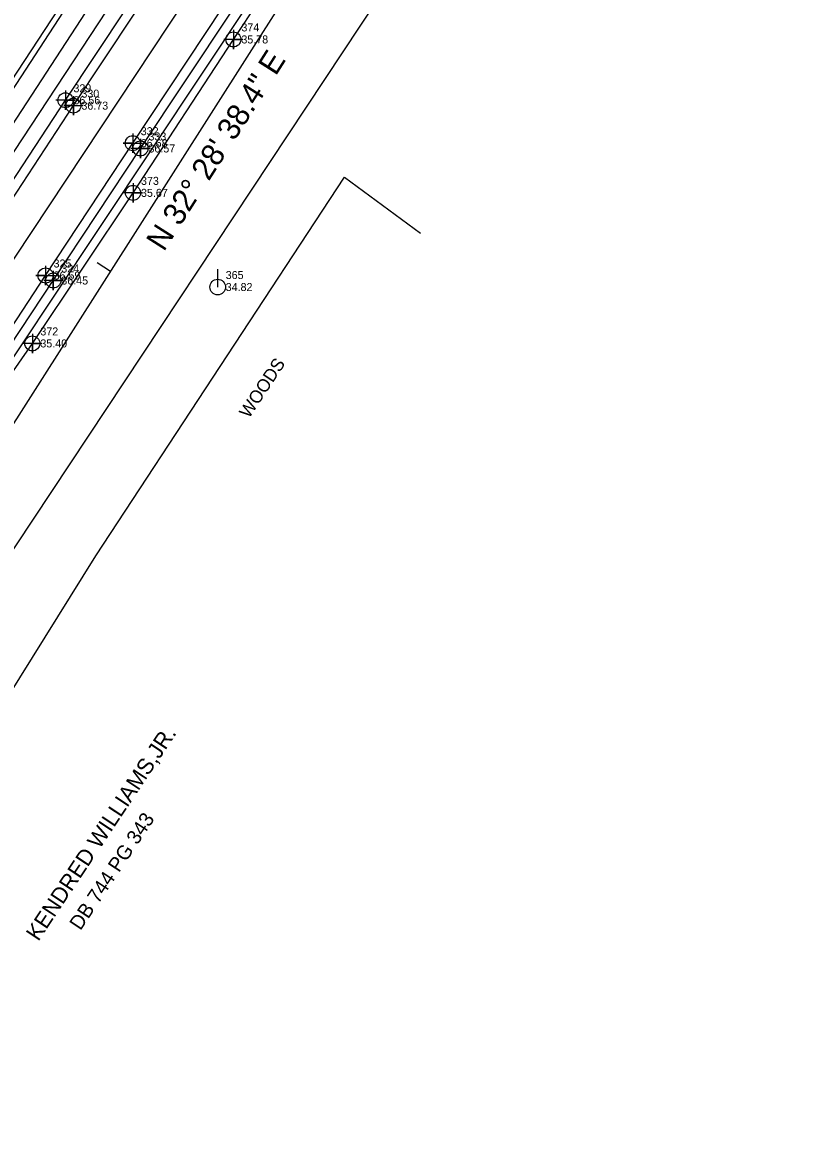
# Model space of a CAD drawing. Extents: x 2603627 to 2605187, y 896619 to 899063.
# Drawn here: x 2604841.7 to 2605082.8, y 898327.7 to 898680.4 of the extents above; entities that cross this region are included whole.
import ezdxf

# ---------------------------------------------------------------- set-up
doc = ezdxf.new("R2010")
doc.units = 0
for name, color, linetype in [('Exist Horizontal Alignment', 7, 'Continuous'), ('Exist Horizontal Baseline Alignment', 7, 'Continuous'), ('Exist Horizontal Baseline Alignment Direction Label', 7, 'Continuous'), ('Exist Horizontal Baseline Alignment Tick small', 7, 'Continuous'), ('Exist Property Deed Book Text', 7, 'Continuous'), ('Exist Property Owner Text', 7, 'Continuous'), ('Exist Right of Way Line', 7, 'Continuous'), ('Exist Roads EOP', 7, 'Continuous'), ('Exist Roads EOP Cogo Elevation', 7, 'Continuous'), ('Exist Roads EOP Cogo Number', 7, 'Continuous'), ('Exist Roads EOP Cogo Point CELL', 7, 'Continuous'), ('Exist Roads EOT', 7, 'Continuous'), ('Exist Roads EOT Cogo Elevation', 7, 'Continuous'), ('Exist Roads EOT Cogo Number', 7, 'Continuous'), ('Exist Roads EOT Cogo Point CELL', 7, 'Continuous'), ('Exist Utilities Power Pole CELL', 7, 'Continuous'), ('Exist Utilities Power Pole Cogo Elevation', 7, 'Continuous'), ('Exist Utilities Power Pole Cogo Number', 7, 'Continuous'), ('Exist Utilities Telephone UG Cable SUE LOS C', 7, 'Continuous'), ('Exist Utilities Telephone UG FO SUE LOS C', 7, 'Continuous'), ('Exist Utilities Water UG Line SUE LOS B', 7, 'Continuous'), ('Exist Utilities Water UG Line SUE LOS B Cogo Elevation', 7, 'Continuous'), ('Exist Utilities Water UG Line SUE LOS B Cogo Number', 7, 'Continuous'), ('Exist Utilities Water UG Line SUE LOS B Cogo Point CELL', 7, 'Continuous'), ('Exist Vegetation Woods Line', 7, 'Continuous'), ('Exist Vegetation Woods Line Text', 7, 'Continuous')]:
    doc.layers.add(name, color=color, linetype=linetype)

# ---------------------------------------------------------------- blocks, each defined once
blk = doc.blocks.new('EXIST ROADS EOP COGO POINT')
at = {"layer": 'Exist Roads EOP Cogo Point CELL'}
blk.add_lwpolyline([(0, 0.06), (0, -0.06), (0, 0), (0.06, 0), (-0.06, 0)], dxfattribs=at)
blk.add_circle((0, 0), 0.0469, dxfattribs=at)
blk = doc.blocks.new('EXIST ROADS EOT COGO POINT')
at = {"layer": 'Exist Roads EOT Cogo Point CELL'}
blk.add_lwpolyline([(0, 0.06), (0, -0.06), (0, 0), (-0.06, 0), (0.06, 0)], dxfattribs=at)
blk.add_circle((0, 0), 0.0469, dxfattribs=at)
blk = doc.blocks.new('EXIST UTILITIES WATER UG LINE SUE LOS B COGO POINT')
at = {"layer": 'Exist Utilities Water UG Line SUE LOS B Cogo Point CELL'}
blk.add_lwpolyline([(0, 0.06), (0, -0.06), (0, 0), (0.06, 0), (-0.06, 0)], dxfattribs=at)
blk.add_circle((0, 0), 0.0469, dxfattribs=at)

msp = doc.modelspace()

# ---------------------------------------------------------------- linework, layer by layer
at = {"layer": 'Exist Horizontal Alignment'}
msp.add_line((2604681.44, 898368.79), (2605041.11, 898911.74), dxfattribs=at)
at = {"layer": 'Exist Horizontal Baseline Alignment'}
msp.add_line((2604793.6, 898483.9), (2605028.26, 898852.56), dxfattribs=at)
at = {"layer": 'Exist Horizontal Baseline Alignment Tick small'}
msp.add_line((2604869.2, 898602.67), (2604864.98, 898605.35), dxfattribs=at)
at = {"layer": 'Exist Right of Way Line'}
msp.add_line((2604723.13, 898341.18), (2605082.79, 898884.13), dxfattribs=at)
at = {"layer": 'Exist Roads EOP'}
for points in [[(2604577.96, 898237.27), (2604606.45, 898281.24), (2604633.89, 898322.5), (2604662.45, 898365.47), (2604690.62, 898408.06), (2604717.29, 898448.09), (2604745.46, 898490.11), (2604773.6, 898532.6), (2604800.88, 898573.95), (2604828.34, 898615.46), (2604855.1, 898656.15), (2604883.53, 898699.09), (2604911.29, 898740.95), (2604939.38, 898783.41), (2604966.33, 898824.04), (2604993.38, 898865.27), (2605022.2, 898908.38), (2605029.46, 898919.46)], [(2604713.86, 898392.44), (2604740.28, 898432.25), (2604768.45, 898474.26), (2604797.27, 898517.92), (2604823.93, 898558.47), (2604851.31, 898599.84), (2604878.52, 898641.09), (2604906.84, 898683.65), (2604934.68, 898725.71), (2604962.63, 898767.92), (2604989.32, 898808.49), (2605016.42, 898849.59), (2605045.34, 898893.33), (2605052.55, 898904.16)]]:
    msp.add_lwpolyline(points, dxfattribs=at)
at = {"layer": 'Exist Roads EOT'}
for points in [[(2604580.65, 898235.67), (2604609.23, 898279.3), (2604636.66, 898320.72), (2604665.18, 898363.91), (2604693.37, 898406.36), (2604719.95, 898446.05), (2604748, 898488.34), (2604776.15, 898530.84), (2604803.5, 898572.3), (2604830.95, 898613.91), (2604857.58, 898654.47), (2604886.02, 898697.38), (2604913.86, 898739.33), (2604942.03, 898781.72), (2604969.06, 898822.38), (2604996.07, 898863.44), (2605024.73, 898906.73), (2605032, 898917.78)], [(2604598.04, 898223.4), (2604627.23, 898267.23), (2604654.64, 898308.57), (2604683.28, 898352.01), (2604711.27, 898394.14), (2604737.98, 898434.05), (2604766.04, 898475.94), (2604794.96, 898519.26), (2604821.61, 898559.82), (2604848.89, 898601.4), (2604876.12, 898642.73), (2604904.4, 898685.35), (2604932.33, 898727.23), (2604960.29, 898769.49), (2604987.32, 898810.19), (2605014.12, 898850.95), (2605043.08, 898894.89), (2605050.2, 898905.72)]]:
    msp.add_lwpolyline(points, dxfattribs=at)
at = {"layer": 'Exist Utilities Power Pole CELL'}
for q in [(2604902.65, 898603.41), (2604902.65, 898597.79)]:
    msp.add_line((2604902.65, 898597.79), q, dxfattribs=at)
msp.add_circle((2604902.65, 898597.79), 2.45, dxfattribs=at)
at = {"layer": 'Exist Utilities Telephone UG Cable SUE LOS C'}
for p, q in [((2604797.03, 898576.37), (2605024.91, 898922.48)), ((2604850.74, 898593.69), (2605031.63, 898865.69)), ((2604658.71, 898389.49), (2604852.96, 898684.66)), ((2604753.32, 898447.21), (2604850.74, 898593.69))]:
    msp.add_line(p, q, dxfattribs=at)
at = {"layer": 'Exist Utilities Telephone UG FO SUE LOS C'}
for p, q in [((2604671.2, 898402.26), (2605014.35, 898929.48)), ((2604676.14, 898398.98), (2605019.3, 898926.2))]:
    msp.add_line(p, q, dxfattribs=at)
at = {"layer": 'Exist Utilities Water UG Line SUE LOS B'}
msp.add_lwpolyline([(2604590.41, 898183.07), (2604608.13, 898210.78), (2604631.33, 898247.72), (2604631.98, 898248.77), (2604637.93, 898260.9), (2604650.01, 898281.75), (2604670.13, 898312.66), (2604706.14, 898370.49), (2604744.2, 898428.79), (2604775.85, 898478.14), (2604817.62, 898541.22), (2604844.76, 898580.18), (2604876.2, 898627.22), (2604907.55, 898675.15), (2604931.69, 898711.47), (2604963.51, 898758.63), (2604991.08, 898800.9), (2605022.23, 898847.26), (2605044.13, 898880.13), (2605057.71, 898900.74)], dxfattribs=at)
at = {"layer": 'Exist Vegetation Woods Line'}
for points in [[(2604864.62, 898513.8), (2604942.25, 898632.13), (2604965.96, 898614.62)], [(2604653.24, 898142.95), (2604632.09, 898155.82), (2604674.87, 898231.68), (2604758.69, 898344.01), (2604864.62, 898513.8)]]:
    msp.add_lwpolyline(points, dxfattribs=at)

# ---------------------------------------------------------------- block references
at = {"layer": 'Exist Roads EOP Cogo Point CELL', "xscale": 50, "yscale": 50}
for p in [(2604855.1, 898656.15), (2604878.52, 898641.09), (2604851.31, 898599.84)]:
    msp.add_blockref('EXIST ROADS EOP COGO POINT', p, dxfattribs=at)
at = {"layer": 'Exist Roads EOT Cogo Point CELL', "xscale": 50, "yscale": 50}
for p in [(2604857.58, 898654.47), (2604876.12, 898642.73), (2604848.89, 898601.4)]:
    msp.add_blockref('EXIST ROADS EOT COGO POINT', p, dxfattribs=at)
at = {"layer": 'Exist Utilities Water UG Line SUE LOS B Cogo Point CELL', "xscale": 50, "yscale": 50}
for p in [(2604907.55, 898675.15), (2604876.2, 898627.22), (2604844.76, 898580.18)]:
    msp.add_blockref('EXIST UTILITIES WATER UG LINE SUE LOS B COGO POINT', p, dxfattribs=at)

# ---------------------------------------------------------------- texts
at = {"layer": 'Exist Horizontal Baseline Alignment Direction Label'}
msp.add_text('N 32%%d 28\' 38.4" E', height=7, rotation=57.5227, dxfattribs=at).set_placement((2604885.83, 898608.64))
at = {"layer": 'Exist Property Deed Book Text'}
msp.add_text('DB 744 PG 343', height=4.5, rotation=56.4133, dxfattribs=at).set_placement((2604859.78, 898396.54))
at = {"layer": 'Exist Property Owner Text'}
msp.add_text('KENDRED WILLIAMS,JR.', height=5, rotation=56.4133, dxfattribs=at).set_placement((2604846.62, 898393.17))
at = {"layer": 'Exist Roads EOP Cogo Elevation'}
for s, p in [('36.56', (2604857.6, 898654.9)), ('36.57', (2604881.02, 898639.84)), ('36.45', (2604853.81, 898598.59))]:
    msp.add_text(s, height=2.5, dxfattribs=at).set_placement(p)
at = {"layer": 'Exist Roads EOP Cogo Number'}
for s, p in [('329', (2604857.6, 898658.65)), ('333', (2604881.02, 898643.59)), ('324', (2604853.81, 898602.34))]:
    msp.add_text(s, height=2.5, dxfattribs=at).set_placement(p)
at = {"layer": 'Exist Roads EOT Cogo Elevation'}
for s, p in [('36.73', (2604860.08, 898653.22)), ('36.68', (2604878.62, 898641.48)), ('36.59', (2604851.39, 898600.15))]:
    msp.add_text(s, height=2.5, dxfattribs=at).set_placement(p)
at = {"layer": 'Exist Roads EOT Cogo Number'}
for s, p in [('330', (2604860.08, 898656.97)), ('332', (2604878.62, 898645.23)), ('325', (2604851.39, 898603.9))]:
    msp.add_text(s, height=2.5, dxfattribs=at).set_placement(p)
at = {"layer": 'Exist Utilities Power Pole Cogo Elevation'}
msp.add_text('34.82', height=2.5, dxfattribs=at).set_placement((2604905.15, 898596.54))
at = {"layer": 'Exist Utilities Power Pole Cogo Number'}
msp.add_text('365', height=2.5, dxfattribs=at).set_placement((2604905.15, 898600.29))
at = {"layer": 'Exist Utilities Water UG Line SUE LOS B Cogo Elevation'}
for s, p in [('35.78', (2604910.05, 898673.9)), ('35.67', (2604878.7, 898625.97)), ('35.40', (2604847.26, 898578.93))]:
    msp.add_text(s, height=2.5, dxfattribs=at).set_placement(p)
at = {"layer": 'Exist Utilities Water UG Line SUE LOS B Cogo Number'}
for s, p in [('374', (2604910.05, 898677.65)), ('373', (2604878.7, 898629.72)), ('372', (2604847.26, 898582.68))]:
    msp.add_text(s, height=2.5, dxfattribs=at).set_placement(p)
at = {"layer": 'Exist Vegetation Woods Line Text'}
msp.add_text('WOODS', height=4, rotation=56.4786, dxfattribs=at).set_placement((2604912.43, 898556.55))

doc.saveas('drawing.dxf')
